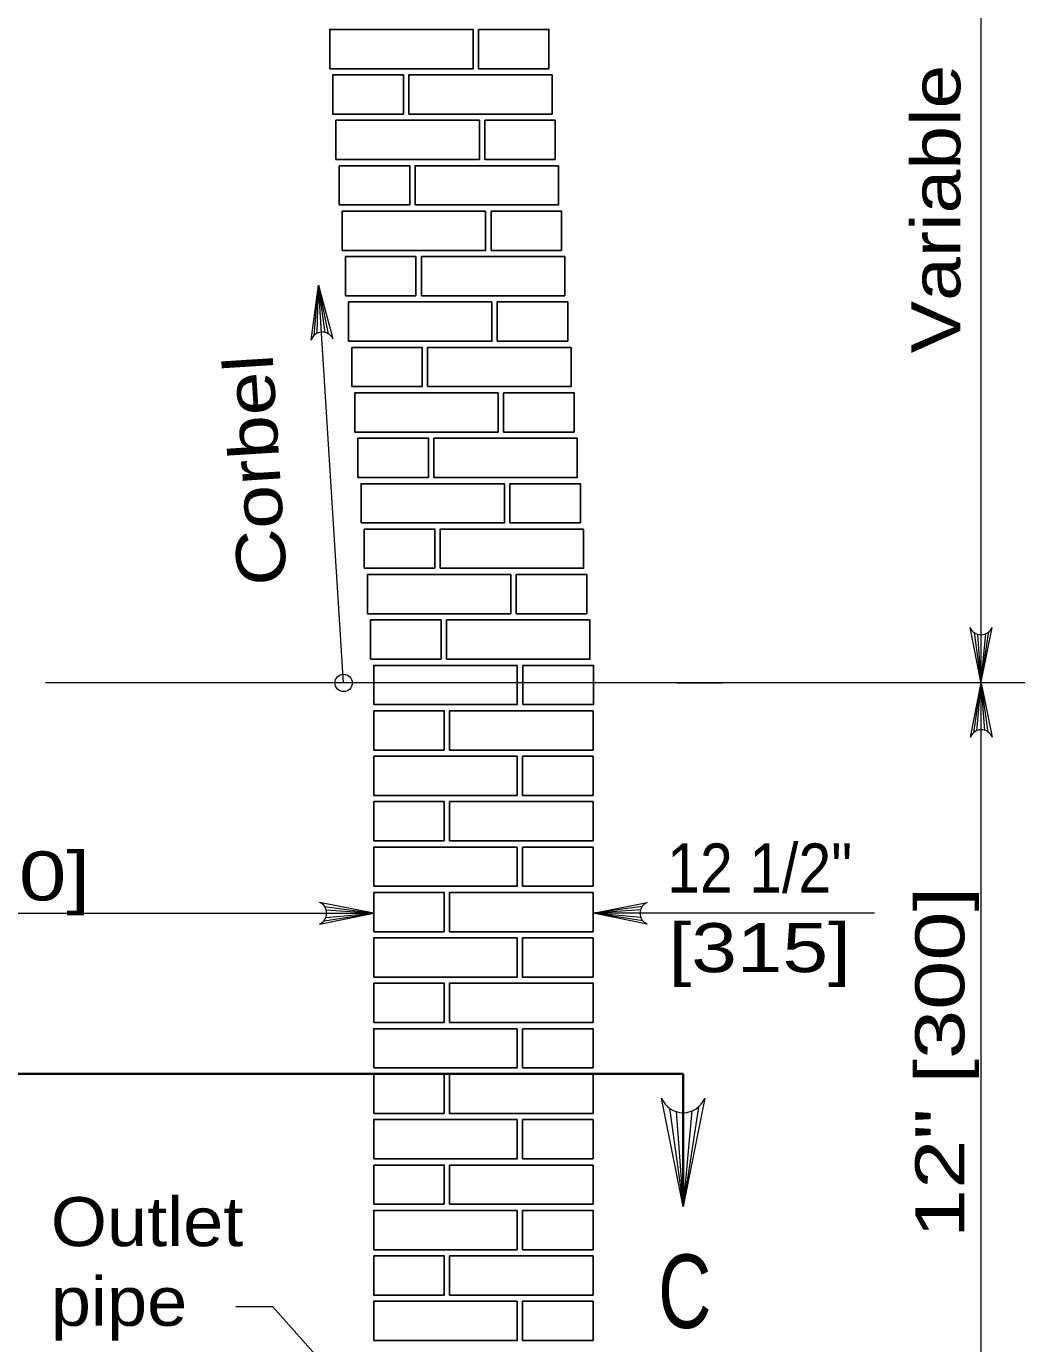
# Model space of a CAD drawing. Extents: x 750.7 to 784.7, y 860.1 to 882.1.
# Drawn here: x 756.786 to 760.016, y 865.553 to 869.853 of the extents above; entities that cross this region are included whole.
import ezdxf
from ezdxf.enums import TextEntityAlignment as Align

# ---------------------------------------------------------------- set-up
doc = ezdxf.new("R2010")
doc.units = 0
doc.header["$LTSCALE"] = 0.064
doc.layers.add('1', color=7, linetype='Continuous', lineweight=13)

msp = doc.modelspace()

# ---------------------------------------------------------------- linework, layer by layer
at = {"layer": '1'}
for p, q in [((759.90117, 865.26633), (759.90117, 870.88433)), ((757.72483, 868.84475), (757.73942, 869.00817)), ((757.73483, 868.8515), (757.73942, 869.00817)), ((757.821, 867.71033), (757.73942, 869.00817)), ((757.749, 868.85525), (757.73942, 869.00817)), ((757.76042, 868.85433), (757.73942, 869.00817)), ((757.77183, 868.84958), (757.73942, 869.00817)), ((759.87775, 867.87458), (759.90017, 867.71425)), ((759.88883, 867.86908), (759.90017, 867.71425)), ((759.92492, 867.87642), (759.90017, 867.71425)), ((759.91458, 867.87033), (759.90017, 867.71425)), ((759.90017, 867.8675), (759.90017, 867.71425)), ((758.90908, 867.71033), (756.84792, 867.71033)), ((762.7415, 867.71042), (758.81575, 867.71033)), ((758.90908, 867.71033), (759.05633, 867.71033)), ((759.87633, 867.54808), (759.90117, 867.71033)), ((759.88675, 867.55425), (759.90117, 867.71033)), ((759.90117, 867.55708), (759.90117, 867.71033)), ((759.9125, 867.55542), (759.90117, 867.71033)), ((759.92358, 867.55), (759.90117, 867.71033)), ((757.75883, 866.98092), (757.91908, 866.9585)), ((758.79483, 866.98092), (758.6345, 866.9585)), ((756.67608, 866.9585), (757.91908, 866.9585)), ((757.75692, 866.93375), (757.91908, 866.9585)), ((757.76308, 866.94408), (757.91908, 866.9585)), ((757.76425, 866.96983), (757.91908, 866.9585)), ((757.76592, 866.9585), (757.91908, 866.9585)), ((758.78942, 866.96983), (758.6345, 866.9585)), ((759.55258, 866.9585), (758.6345, 866.9585)), ((758.78775, 866.9585), (758.6345, 866.9585)), ((758.79058, 866.94408), (758.6345, 866.9585)), ((758.79667, 866.93375), (758.6345, 866.9585)), ((758.88375, 866.32167), (758.92867, 866.001)), ((758.906, 866.31075), (758.92867, 866.001)), ((758.97825, 866.32542), (758.92867, 866.001)), ((758.95742, 866.31317), (758.92867, 866.001)), ((758.92867, 866.3075), (758.92867, 866.001))]:
    msp.add_line(p, q, dxfattribs=at)
at = {"layer": '1', "lineweight": 25}
for p, q in [((758.26083, 869.71517), (758.26083, 869.84325)), ((757.78575, 869.56692), (757.78575, 869.69492)), ((758.49092, 869.71517), (758.26083, 869.71517)), ((758.01592, 869.56692), (757.78575, 869.56692)), ((758.28133, 869.41867), (758.28133, 869.54667)), ((757.80633, 869.27033), (757.80625, 869.39842)), ((758.5115, 869.41867), (758.28133, 869.41867)), ((758.03642, 869.27033), (757.80633, 869.27033)), ((758.30183, 869.12208), (758.30183, 869.25017)), ((757.82683, 868.97383), (757.82683, 869.10192)), ((758.532, 869.12208), (758.30183, 869.12208)), ((758.05692, 868.97383), (757.82683, 868.97383)), ((758.32233, 868.82558), (758.32233, 868.95358)), ((757.84733, 868.67733), (757.84733, 868.80533)), ((758.5525, 868.82558), (758.32233, 868.82558)), ((758.07742, 868.67733), (757.84733, 868.67733)), ((758.34283, 868.52908), (758.34283, 868.65708)), ((758.573, 868.52908), (758.34283, 868.52908)), ((757.86783, 868.38075), (757.86783, 868.50883)), ((758.098, 868.38075), (757.86783, 868.38075)), ((758.36342, 868.2325), (758.36342, 868.36058)), ((758.5935, 868.2325), (758.36342, 868.2325)), ((757.88833, 868.08425), (757.88833, 868.21225)), ((758.1185, 868.08425), (757.88833, 868.08425)), ((758.38392, 867.936), (758.38392, 868.064)), ((758.614, 867.936), (758.38392, 867.936)), ((757.90883, 867.78767), (757.90883, 867.91575)), ((758.139, 867.78767), (757.90883, 867.78767)), ((758.40567, 867.63942), (758.40567, 867.7675)), ((758.63583, 867.63942), (758.40567, 867.63942)), ((757.91908, 867.49117), (757.91908, 867.61925)), ((758.14925, 867.49117), (757.91908, 867.49117)), ((758.40433, 867.34292), (758.40433, 867.471)), ((758.38683, 867.36983), (758.38683, 867.42175)), ((758.40433, 867.36983), (758.40433, 867.42467)), ((757.91908, 867.19467), (757.91908, 867.32267)), ((758.6345, 867.34292), (758.40433, 867.34292)), ((758.14925, 867.19467), (757.91908, 867.19467)), ((758.40433, 867.04642), (758.40433, 867.17442)), ((757.91908, 866.89808), (757.91908, 867.02617)), ((758.6345, 867.04642), (758.40433, 867.04642)), ((758.14925, 866.89808), (757.91908, 866.89808)), ((758.40433, 866.74983), (758.40433, 866.87792)), ((758.38683, 866.77683), (758.38683, 866.82867)), ((758.40433, 866.77683), (758.40433, 866.83158)), ((757.91908, 866.60158), (757.91908, 866.72967)), ((758.6345, 866.74983), (758.40433, 866.74983)), ((758.14925, 866.60158), (757.91908, 866.60158)), ((758.40433, 866.45333), (758.40433, 866.58133)), ((757.91908, 866.30508), (757.91908, 866.43308)), ((758.6345, 866.45333), (758.40433, 866.45333)), ((758.14925, 866.30508), (757.91908, 866.30508)), ((758.40433, 866.15675), (758.40433, 866.28483)), ((757.91908, 866.0085), (757.91908, 866.13658)), ((758.6345, 866.15675), (758.40433, 866.15675)), ((758.14925, 866.0085), (757.91908, 866.0085)), ((758.40433, 865.86025), (758.40433, 865.98833)), ((758.6345, 865.86025), (758.40433, 865.86025)), ((757.91908, 865.712), (757.91908, 865.84)), ((758.14925, 865.712), (757.91908, 865.712)), ((758.40433, 865.56375), (758.40433, 865.69175)), ((758.6345, 865.56375), (758.40433, 865.56375))]:
    msp.add_line(p, q, dxfattribs=at)
at = {"layer": '1', "lineweight": 35}
for p, q in [((758.92867, 866.43383), (753.73875, 866.43375)), ((758.92867, 866.001), (758.92867, 866.43383))]:
    msp.add_line(p, q, dxfattribs=at)
at = {"layer": '1', "lineweight": 25}
for points in [[(757.7755, 869.71517), (757.7755, 869.84325), (758.24317, 869.84325)], [(757.7755, 869.71517), (758.24317, 869.71517), (758.24317, 869.84325)], [(758.49092, 869.71517), (758.49092, 869.84325), (758.26083, 869.84325)], [(758.01592, 869.56692), (758.01592, 869.69492), (757.78575, 869.69492)], [(758.0335, 869.56692), (758.0335, 869.695), (758.50117, 869.69492)], [(758.0335, 869.56692), (758.50117, 869.56692), (758.50117, 869.69492)], [(757.796, 869.41858), (757.796, 869.54667), (758.26375, 869.54667)], [(757.796, 869.41858), (758.26375, 869.41858), (758.26375, 869.54667)], [(758.5115, 869.41867), (758.51142, 869.54667), (758.28133, 869.54667)], [(758.03642, 869.27033), (758.03642, 869.39842), (757.80625, 869.39842)], [(758.054, 869.27033), (758.054, 869.39842), (758.52175, 869.39842)], [(758.054, 869.27033), (758.52175, 869.27033), (758.52175, 869.39842)], [(757.81658, 869.12208), (757.81658, 869.25017), (758.28425, 869.25017)], [(757.81658, 869.12208), (758.28425, 869.12208), (758.28425, 869.25017)], [(758.532, 869.12208), (758.532, 869.25017), (758.30183, 869.25017)], [(758.05692, 868.97383), (758.05692, 869.10192), (757.82683, 869.10192)], [(758.07458, 868.97383), (758.07458, 869.10192), (758.54225, 869.10192)], [(758.07458, 868.97383), (758.54225, 868.97383), (758.54225, 869.10192)], [(757.83708, 868.82558), (757.83708, 868.95358), (758.30475, 868.95358)], [(757.83708, 868.82558), (758.30475, 868.82558), (758.30475, 868.95358)], [(758.5525, 868.82558), (758.5525, 868.95358), (758.32233, 868.95358)], [(758.07742, 868.67733), (758.07742, 868.80533), (757.84733, 868.80533)], [(758.09508, 868.67733), (758.09508, 868.80533), (758.56275, 868.80533)], [(758.09508, 868.67733), (758.56275, 868.67733), (758.56275, 868.80533)], [(757.85758, 868.529), (757.85758, 868.65708), (758.32525, 868.65708)], [(757.85758, 868.529), (758.32525, 868.529), (758.32525, 868.65708)], [(758.573, 868.52908), (758.573, 868.65708), (758.34283, 868.65708)], [(758.098, 868.38075), (758.098, 868.50883), (757.86783, 868.50883)], [(758.11558, 868.38075), (758.11558, 868.50883), (758.58325, 868.50883)], [(758.11558, 868.38075), (758.58325, 868.38075), (758.58325, 868.50883)], [(757.87808, 868.2325), (757.87808, 868.36058), (758.34575, 868.36058)], [(757.87808, 868.2325), (758.34575, 868.2325), (758.34575, 868.36058)], [(758.5935, 868.2325), (758.5935, 868.36058), (758.36342, 868.36058)], [(758.1185, 868.08425), (758.1185, 868.21225), (757.88833, 868.21225)], [(758.13608, 868.08425), (758.13608, 868.21233), (758.60375, 868.21233)], [(758.13608, 868.08425), (758.60375, 868.08425), (758.60375, 868.21233)], [(757.89858, 867.936), (757.89858, 868.064), (758.36625, 868.064)], [(757.89858, 867.936), (758.36625, 867.936), (758.36625, 868.064)], [(758.614, 867.936), (758.614, 868.064), (758.38392, 868.064)], [(758.139, 867.78767), (758.139, 867.91575), (757.90883, 867.91575)], [(758.15658, 867.78767), (758.15658, 867.91575), (758.62425, 867.91575)], [(758.15658, 867.78767), (758.62425, 867.78767), (758.62425, 867.91575)], [(757.91908, 867.63942), (757.91908, 867.7675), (758.38683, 867.7675)], [(757.91908, 867.63942), (758.38683, 867.63942), (758.38683, 867.7675)], [(758.63583, 867.63942), (758.63583, 867.7675), (758.40567, 867.7675)], [(758.14925, 867.49117), (758.14925, 867.61925), (757.91908, 867.61925)], [(758.16683, 867.49117), (758.16683, 867.61925), (758.63458, 867.61925)], [(758.16683, 867.49117), (758.63458, 867.49117), (758.63458, 867.61925)], [(757.91908, 867.34292), (757.91908, 867.471), (758.38683, 867.471)], [(757.91908, 867.34292), (758.38683, 867.34292), (758.38683, 867.471)], [(758.6345, 867.34292), (758.6345, 867.471), (758.40433, 867.471)], [(758.14925, 867.19467), (758.14925, 867.32267), (757.91908, 867.32267)], [(758.16683, 867.19467), (758.16683, 867.32275), (758.63458, 867.32275)], [(758.16683, 867.19467), (758.63458, 867.19467), (758.63458, 867.32275)], [(757.91908, 867.04642), (757.91908, 867.17442), (758.38683, 867.17442)], [(757.91908, 867.04642), (758.38683, 867.04642), (758.38683, 867.17442)], [(758.6345, 867.04642), (758.6345, 867.17442), (758.40433, 867.17442)], [(758.14925, 866.89808), (758.14925, 867.02617), (757.91908, 867.02617)], [(758.16683, 866.89808), (758.16683, 867.02617), (758.63458, 867.02617)], [(758.16683, 866.89808), (758.63458, 866.89817), (758.63458, 867.02617)], [(757.91908, 866.74983), (757.91908, 866.87792), (758.38683, 866.87792)], [(757.91908, 866.74983), (758.38683, 866.74983), (758.38683, 866.87792)], [(758.6345, 866.74983), (758.6345, 866.87792), (758.40433, 866.87792)], [(758.14925, 866.60158), (758.14925, 866.72967), (757.91908, 866.72967)], [(758.16683, 866.60158), (758.16683, 866.72967), (758.63458, 866.72967)], [(758.16683, 866.60158), (758.63458, 866.60158), (758.63458, 866.72967)], [(757.91908, 866.45333), (757.91908, 866.58133), (758.38683, 866.58133)], [(757.91908, 866.45333), (758.38683, 866.45333), (758.38683, 866.58133)], [(758.6345, 866.45333), (758.6345, 866.58133), (758.40433, 866.58133)], [(758.14925, 866.30508), (758.14925, 866.43308), (757.91908, 866.43308)], [(758.16683, 866.30508), (758.16683, 866.43308), (758.63458, 866.43308)], [(758.16683, 866.30508), (758.63458, 866.30508), (758.63458, 866.43308)], [(757.91908, 866.15675), (757.91908, 866.28483), (758.38683, 866.28483)], [(757.91908, 866.15675), (758.38683, 866.15675), (758.38683, 866.28483)], [(758.6345, 866.15675), (758.6345, 866.28483), (758.40433, 866.28483)], [(758.14925, 866.0085), (758.14925, 866.13658), (757.91908, 866.13658)], [(758.16683, 866.0085), (758.16683, 866.13658), (758.63458, 866.13658)], [(758.16683, 866.0085), (758.63458, 866.0085), (758.63458, 866.13658)], [(757.91908, 865.86025), (757.91908, 865.98833), (758.38683, 865.98833)], [(757.91908, 865.86025), (758.38683, 865.86025), (758.38683, 865.98833)], [(758.6345, 865.86025), (758.6345, 865.98833), (758.40433, 865.98833)], [(758.14925, 865.712), (758.14925, 865.84), (757.91908, 865.84)], [(758.16683, 865.712), (758.16683, 865.84008), (758.63458, 865.84008)], [(758.16683, 865.712), (758.63458, 865.712), (758.63458, 865.84008)], [(757.91908, 865.56375), (757.91908, 865.69175), (758.38683, 865.69175)], [(757.91908, 865.56375), (758.38683, 865.56375), (758.38683, 865.69175)], [(758.6345, 865.56375), (758.6345, 865.69175), (758.40433, 865.69175)]]:
    msp.add_lwpolyline(points, dxfattribs=at)
at = {"layer": '1'}
for points in [[(757.71517, 868.82925), (757.73942, 869.00817), (757.78583, 868.83367)], [(759.93558, 867.89133), (759.90017, 867.71425), (759.86475, 867.89133)], [(759.86575, 867.53325), (759.90117, 867.71033), (759.93658, 867.53325)], [(757.74208, 866.92308), (757.91908, 866.9585), (757.74208, 866.99392)], [(758.81158, 866.92308), (758.6345, 866.9585), (758.81158, 866.99392)], [(758.9995, 866.35517), (758.92867, 866.001), (758.85783, 866.35517)], [(757.92242, 865.29892), (757.58958, 865.67383), (757.46925, 865.67383)]]:
    msp.add_lwpolyline(points, dxfattribs=at)
msp.add_circle((757.821, 867.71035), 0.02833, dxfattribs=at)
for centre, radius, start, end in [((757.75146, 868.81719), 0.03822, 25.68463, 161.51076), ((759.90011, 867.90562), 0.03822, 202.08782, 337.91395), ((759.90119, 867.51893), 0.03822, 22.08782, 157.91395), ((757.72774, 866.95855), 0.03822, 292.08605, 67.91218), ((758.82587, 866.95855), 0.03822, 112.08782, 247.91395), ((758.9286, 866.38378), 0.07644, 202.08782, 337.91395)]:
    msp.add_arc(centre, radius, start, end, dxfattribs=at)

# ---------------------------------------------------------------- texts
for s, rotation, width, p in [('Variable', 90, 1.2, (759.83267, 868.78592)), ('Corbel', 93.597, 1.2, (757.63633, 868.0325)), ('12" [300]', 90, 1.35, (759.84583, 865.89808))]:
    msp.add_text(s, height=0.16, rotation=rotation, dxfattribs=dict(at, width=width)).set_placement(p)
for s, width, p in [('12 1/2"', 0.9, (759.17817, 867.02608)), ('[315]', 1.25, (759.17813, 866.76608))]:
    msp.add_text(s, height=0.16, dxfattribs=dict(at, width=width)).set_placement(p, align=Align.CENTER)
for s, height, width, p in [('4\'-6" [1370]', 0.16, 1.3, (755.58925, 867.00008)), ('Outlet', 0.16, 1.1, (756.86583, 865.87175)), ('C', 0.24, 0.75, (758.847, 865.60458)), ('pipe', 0.16, 1.1, (756.86583, 865.61175))]:
    msp.add_text(s, height=height, dxfattribs=dict(at, width=width)).set_placement(p)

doc.saveas('drawing.dxf')
